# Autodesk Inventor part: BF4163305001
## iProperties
Shininess: 64.0
Angle Display Precision: 2
Document Length Units: 11272
Document Angle Units: 11279
Document Time Units: 11290
Document Mass Units: 11286
Document Length Units Precision: 3
Document Angle Units Precision: 2
Created: 2003-05
Part Number: BF4163305001
Material: Bronze, Soft Tin
Description: 1/8 CROSS, RED BRASS, 125 LB, NPT
Vendor: BF4163305001
Document SubType Name: Modeling
Designer: RCOPE
Density: 8.874
Volumn: 4.5651713197404264
Area: 33.2729562570498
PropertySet Name: Model Information
Control State: 0
Master: False
Checked Out: False
Author: RCOPE
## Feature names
1. Revolution1
2. Revolution2
3. Revolution3
4. Mirror1
5. Extrusion8
6. Extrusion9
7. Extrusion10
8. Circular Pattern1
9. Extrusion11
10. Extrusion12
11. Fillet3
12. Fillet4
